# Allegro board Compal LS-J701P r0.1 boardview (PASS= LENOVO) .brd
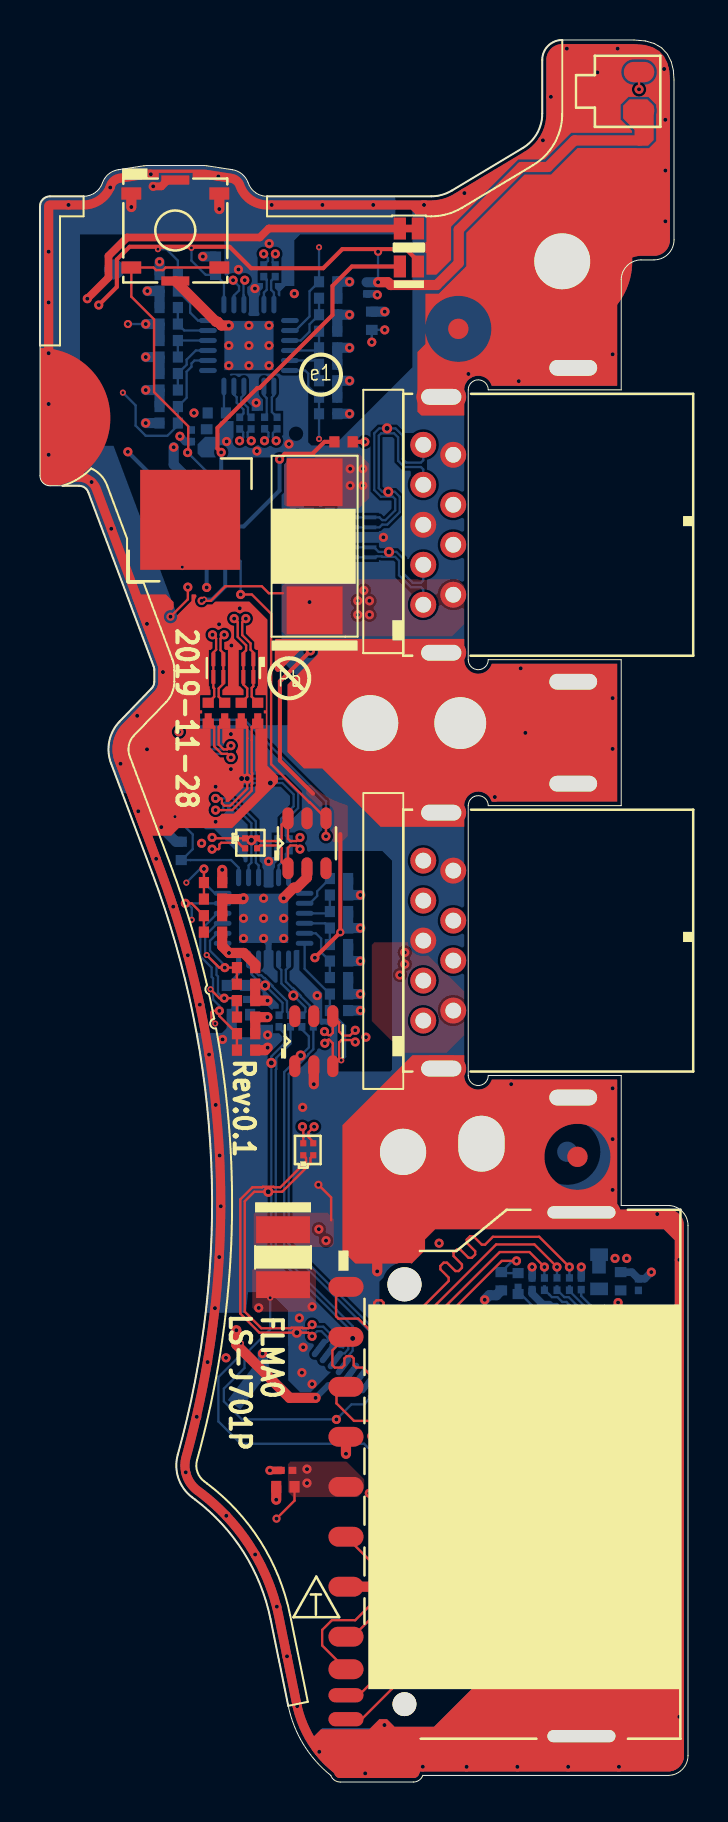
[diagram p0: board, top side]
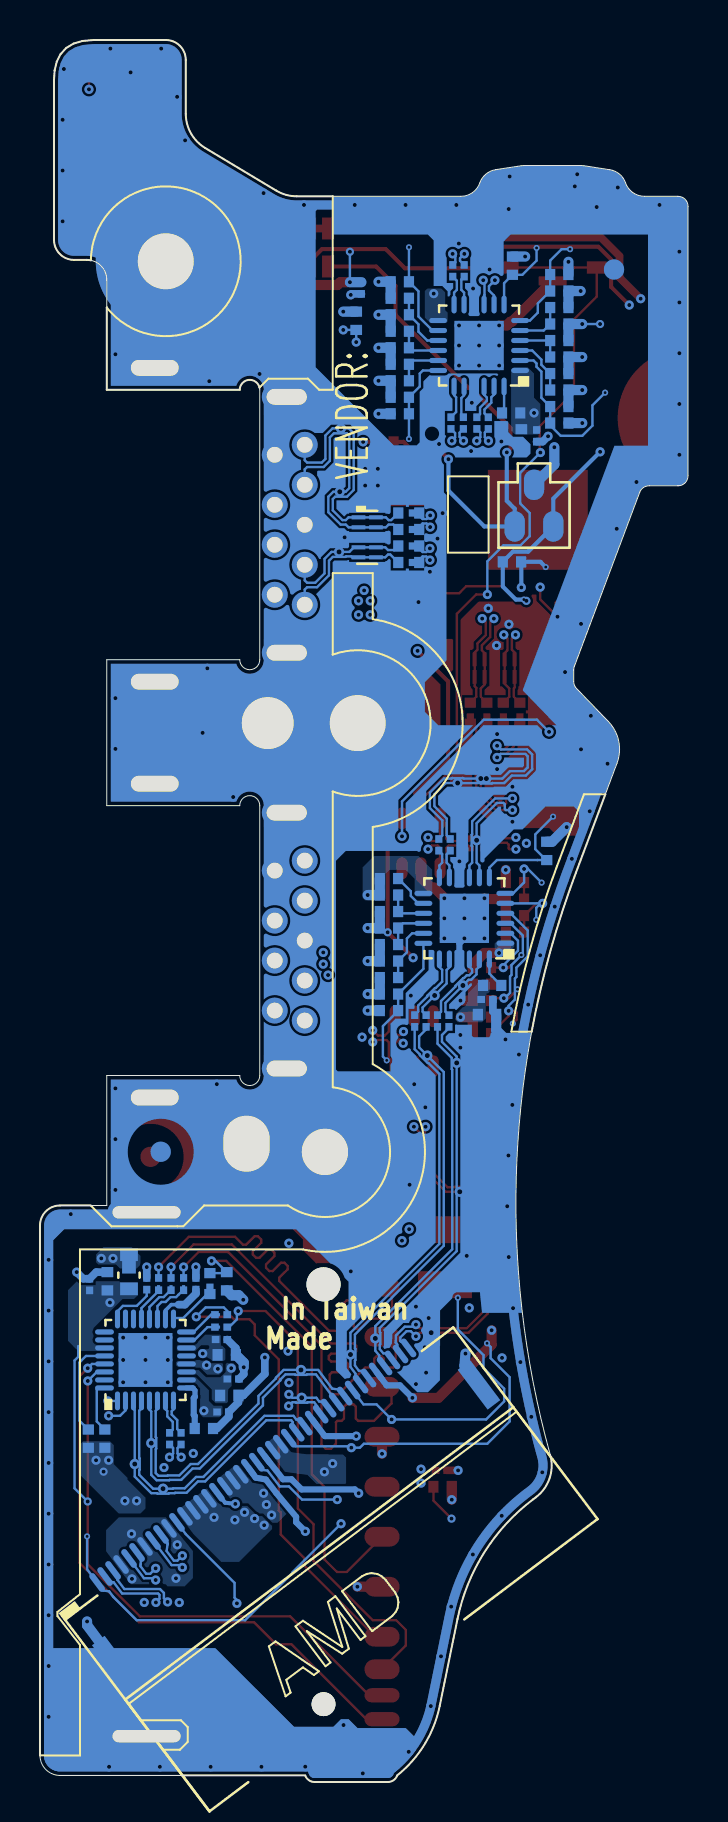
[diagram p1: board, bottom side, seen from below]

Outline 32.41 x 87.14 mm; copper layers: TOP, GND1, IN1, GND2, IN2, IN3, GND3, BOTTOM. Coordinates in mm from the lower left corner of the outline.
Outline path: 0,78.82 arc(0.15,79.17) 0.5,79.32 2.18,79.32 arc(2.76,79.5) 3.12,79.99 arc(3.43,80.43) 3.91,80.65 5.19,80.85 arc(5.27,80.86) 5.34,80.86 8.19,80.86 arc(8.27,80.86) 8.34,80.85 9.62,80.65 arc(10.11,80.43) 10.41,79.99 arc(10.78,79.5) 11.36,79.32 19.56,79.32 arc(20.1,79.39) 20.59,79.6 24.15,81.74 arc(24.86,82.47) 25.12,83.45 25.12,86.14 arc(25.41,86.85) 26.12,87.14 29.71,87.14 30.29,87.09 30.73,86.96 31.09,86.74 31.38,86.43 31.57,86.05 31.67,85.62 31.71,85.14 31.71,77.14 arc(31.41,76.43) 30.71,76.14 30.07,76.14 arc(29.36,75.85) 29.07,75.14 29.07,69.64 22.42,69.64 arc(21.92,70.14) 21.42,69.64 21.42,56.14 arc(21.92,55.64) 22.42,56.14 29.07,56.14 29.07,48.84 22.42,48.84 arc(21.92,49.34) 21.42,48.84 21.42,35.34 arc(21.92,34.84) 22.42,35.34 29.07,35.34 29.07,28.84 31.41,28.84 arc(32.11,28.55) 32.41,27.84 32.41,1.33 arc(32.11,0.62) 31.41,0.33 19.14,0.33 arc(18.96,0.09) 18.67,0 15.01,0 arc(14.73,0.09) 14.54,0.33 arc(13.17,1.88) 12.42,3.81 11.53,8.15 arc(10.19,11.49) 7.75,14.14 7.61,14.24 arc(6.92,15.19) 6.89,16.37 arc(8.56,31.02) 5.61,45.47 3.55,50.96 arc(3.47,52.07) 3.99,53.05 5.58,54.7 arc(5.68,54.86) 5.72,55.05 5.72,55.63 arc(5.71,55.72) 5.69,55.8 2.42,64.52 arc(2.23,64.75) 1.95,64.84 0.5,64.84 arc(0.15,64.99) 0,65.34 0,78.82

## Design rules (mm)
net group CLK: nets CLK_PCIE_N4 CLK_PCIE_P4
net group PCIE: nets PCIE_CRX_C_DTX_N9 PCIE_CRX_C_DTX_P9 PCIE_CRX_DTX_N9 PCIE_CRX_DTX_P9 PCIE_CTX_DRX_N9 PCIE_CTX_DRX_P9
net group USB3: nets USB3_CRX_C_RD_DTX_N1 USB3_CRX_C_RD_DTX_N2 USB3_CRX_C_RD_DTX_P1 USB3_CRX_C_RD_DTX_P2 USB3_CRX_DTX_N1 USB3_CRX_DTX_N2 USB3_CRX_DTX_P1 USB3_CRX_DTX_P2 USB3_CTX_C_RD_DRX_N1 USB3_CTX_C_RD_DRX_N2 USB3_CTX_C_RD_DRX_P1 USB3_CTX_C_RD_DRX_P2 USB3_CTX_DRX_N1 USB3_CTX_DRX_N2 USB3_CTX_DRX_P1 USB3_CTX_DRX_P2 USB3_RX3_CONN1_N1 USB3_RX3_CONN1_N1_R USB3_RX3_CONN1_P1 USB3_RX3_CONN1_P1_R USB3_RX3_CONN2_N2 USB3_RX3_CONN2_N2_R USB3_RX3_CONN2_P2 USB3_RX3_CONN2_P2_R USB3_TX3_CONN1_N1 USB3_TX3_CONN1_N1_R USB3_TX3_CONN1_P1 USB3_TX3_CONN1_P1_R USB3_TX3_CONN2_N2 USB3_TX3_CONN2_N2_R USB3_TX3_CONN2_P2 USB3_TX3_CONN2_P2_R USB3_TX3_MUX_N1_C USB3_TX3_MUX_N2_C USB3_TX3_MUX_P1_C USB3_TX3_MUX_P2_C
net group USB20: nets USB20_N1 USB20_N1_R USB20_N2 USB20_N2_R USB20_P1 USB20_P1_R USB20_P2 USB20_P2_R

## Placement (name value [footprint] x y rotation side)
CHS2  10P_0402_50V8J  [C_0402]  16.59 72.64 90 bottom
CHS3  0.1U_0201_10V6K  [C_0201]  16.33 74.44 90 bottom
CR1  0.1U_0201_10V K X5R  [C_0201]  25.93 16.88 90 bottom
CR2  0.1U_0201_10V K X5R  [C_0201]  25.35 16.88 90 bottom
CR3  0.1U_0201_10V6K  [C_0201]  23.04 20.16 180 bottom
CR4  4.7U_0402_6.3V6M  [C_0402]  29.04 24.59 90 bottom
CR5  10U_0402_6.3V6M  [C_0402]  23.4 19.33 180 bottom
CR6  0.1U_0201_10V6K  [C_0201]  23.55 18.51 180 bottom
CR7  4.7U_0402_6.3V6M  [C_0402]  23.53 21.37 180 bottom
CR8  0.1U_0201_10V6K  [C_0201]  23.63 22.13 180 bottom
CR9  1U_0201_6.3V6M  [C_0201]  24.61 24.63 90 bottom
CR12  5P_0402_50V8C  [C_0402]  23.07 25.51 270 bottom
CR13  0.1U_0201_10V6K  [C_0201]  29.93 24.59 90 bottom
CR14  1U_0201_6.3V6M  [C_0201]  27.07 24.63 90 bottom
CR15  4.7U_0402_6.3V6M  [C_0402]  12.73 14.77 180 top
CR16  0.1U_0201_10V K X5R  [C_0201]  12.63 15.59 180 top
CT11  0.01U_0402_16V7K  [C_0402]  8.34 67.67 270 bottom
CT12  0.1U_0201_10V K X5R  [C_0201]  11.86 68.27 270 bottom
CT13  0.1U_0201_10V K X5R  [C_0201]  11.23 68.27 270 bottom
CT14  0.1U_0201_10V K X5R  [C_0201]  7.57 67.63 270 bottom
CT15  0.1U_0201_10V K X5R  [C_0201]  10.56 67.68 90 bottom
CT16  0.1U_0201_10V K X5R  [C_0201]  9.99 67.68 90 bottom
CT17  0.1U_0201_10V K X5R  [C_0201]  11.77 75.3 90 bottom
CT18  0.1U_0201_10V K X5R  [C_0201]  11.19 75.3 90 bottom
CT23  0.01U_0402_16V7K  [C_0402]  10.51 38.38 180 bottom
CT24  0.1U_0201_10V K X5R  [C_0201]  12.46 46.59 90 bottom
CT25  0.1U_0201_10V K X5R  [C_0201]  11.89 46.59 90 bottom
CT26  0.1U_0201_10V K X5R  [C_0201]  10.34 39.15 180 bottom
CT27  0.1U_0201_10V K X5R  [C_0201]  12.53 37.77 90 bottom
CT28  0.1U_0201_10V K X5R  [C_0201]  11.96 37.77 90 bottom
CT29  0.1U_0201_10V K X5R  [C_0201]  13.1 38.36 270 bottom
CT30  0.1U_0201_10V K X5R  [C_0201]  13.67 38.36 270 bottom
CU31  150U_D2_6.3VM  [C_D2]  13.73 58.62 90 top
CU32  150U_B2_6.3VM_R35M  [C_B2]  12.16 27.63 90 top
D1  -  [L05ESDL5V0NA-4_SLP2510P8-10-9]  16.48 63.26 90 bottom
D2  AZC399-04S  [AZC099-04SPR7G_SOT23-6]  12.4 45.71 0 top
D3  -  [L05ESDL5V0NA-4_SLP2510P8-10-9]  10.67 56.16 0 top
D4  AZ5125-02S.R7G_SOT23-3  [AZ5125-02SPR7G_SOT23-3]  7.7 64.89 0 bottom
D5  AZC399-04S  [AZC099-04SPR7G_SOT23-6]  12.74 35.81 0 top
FD1  CF  [FIDUCIAL_C40M80]  20.92 72.69 0 top
FD2  CF  [FIDUCIAL_C40M80]  26.88 31.27 0 top
FD3  CF  [FIDUCIAL_C40M80]  3.7 75.66 180 bottom
FD4  CF  [FIDUCIAL_C40M80]  26.37 31.53 180 bottom
H1  HOLEA  [H_2P8]  26.12 76.07 0 top
H2  HOLEA  [H_2P8]  16.52 52.97 0 top
H3  HOLEA  [H_2P6]  21.02 52.97 0 top
H4  HOLEA  [H_2P3]  18.16 31.52 0 top
H5  HOLEA  [H_2P8X2P3]  22.08 31.93 90 top
JIO2  TWVM FPC0518-40RC-TAGHT 40P P.5  [HRS_TF31-40S-0P5SH-800_40P]  29.55 9.98 143 bottom
JSD1  T-SOL_156-1001902605~D  [T-SOL_156-1001902605_11P]  15.3 22.27 90 top
JUSB1  ACON_TAR2D-9U1397  [ACON_TAR2D-9U1397_9P]  20.67 59.39 90 top
JUSB2  ACON_TAR2D-9U1397  [ACON_TAR2D-9U1397_9P]  20.67 38.59 90 top
L1  DLM0NSN900HY2D_4P  [MURAT_DLM0NSN900HY2D_4P]  10.26 47.21 0 top
L2  DLM0NSN900HY2D_4P  [MURAT_DLM0NSN900HY2D_4P]  13.17 31.35 90 top
LED3  19-223-S2T1D-C30-2T_ORG-WHITE  [LED_19-223-S2T1D-C30-2T_4P]  18.9 75.81 90 top
NOREF  -  []  7.51 63.14 0 top
NOREF#2  -  []  -151.75 18.89 0 top
NOREF#3  -  []  -20.43 128.05 0 top
NOREF#4  -  []  3.76 -77.88 0 top
NOREF#5  -  []  26.12 76.07 0 top
NOREF#6  -  []  -161.91 14.7 0 top
NOREF#7  -  []  -139.94 19.02 0 top
NOREF#8  -  []  -9.51 85.12 0 top
RR1  6.2K_0402_1%  [R_0402]  24.67 17.68 180 bottom
RR2  10K_0402_5%  [R_0402]  29.99 17.63 270 bottom
RR3  0_0402_5%  [R0402_0OHM]  23.91 24.54 90 bottom
RR4  10K_0402_5%  [R_0402]  29.16 16.72 90 bottom
RR5  0_0603_5%  [R0603_0OHM]  27.96 26.07 270 bottom
RR6  0_0201_5%  [R0201_0OHM]  23.63 23.38 180 bottom
RR7  0_0201_5%  [R0201_0OHM]  23.63 22.75 180 bottom
RR8  0_0201_5%  [R0201_0OHM]  25.85 24.63 90 bottom
RR9  0_0201_5%  [R0201_0OHM]  26.48 24.63 90 bottom
RR10  0_0201_5%  [R0201_0OHM]  25.23 24.63 90 bottom
RS1  412_0402_1%  [R_0402]  8.35 61.04 0 bottom
RS2  412_0402_1%  [R_0402]  15.64 67.04 180 top
RT1  4.99K_0402_1%  [R_0402]  8.78 75.39 90 bottom
RT2  4.7K_0402_5%  [R_0402]  6.89 73.76 180 bottom
RT13  4.7K_0402_5%  [R_0402]  14.87 70.92 180 bottom
RT14  4.7K_0402_5%  [R_0402]  13.96 70.09 0 bottom
RT15  4.7K_0402_5%  [R_0402]  14.87 74.22 180 bottom
RT16  4.7K_0402_5%  [R_0402]  13.96 73.39 0 bottom
RT17  4.7K_0402_5%  [R_0402]  14.87 71.74 180 bottom
RT18  4.7K_0402_5%  [R_0402]  13.96 72.57 0 bottom
RT19  4.7K_0402_5%  [R_0402]  14.87 68.44 180 bottom
RT20  4.7K_0402_5%  [R_0402]  13.96 69.27 0 bottom
RT21  4.7K_0402_5%  [R_0402]  5.98 68.8 0 bottom
RT22  4.7K_0402_5%  [R_0402]  6.89 67.98 180 bottom
RT23  4.7K_0402_5%  [R_0402]  5.98 72.11 0 bottom
RT24  4.7K_0402_5%  [R_0402]  6.89 71.28 180 bottom
RT25  4.7K_0402_5%  [R_0402]  5.98 69.63 0 bottom
RT26  4.7K_0402_5%  [R_0402]  6.89 70.45 180 bottom
RT27  4.7K_0402_5%  [R_0402]  5.98 75.41 0 bottom
RT28  4.7K_0402_5%  [R_0402]  6.89 74.58 180 bottom
RT29  4.7K_0402_5%  [R_0402]  14.87 75.05 180 bottom
RT30  4.7K_0402_5%  [R_0402]  8.39 68.48 0 bottom
RT31  4.7K_0402_5%  [R_0402]  5.98 72.93 0 bottom
RT32  4.99K_0402_1%  [R_0402]  7.07 46.12 90 bottom
RT33  4.7K_0402_5%  [R_0402]  8.2 43.34 0 top
RT34  4.7K_0402_5%  [R_0402]  15.41 41.07 180 bottom
RT35  4.7K_0402_5%  [R_0402]  14.5 40.24 0 bottom
RT36  4.7K_0402_5%  [R_0402]  15.41 44.37 180 bottom
RT37  4.7K_0402_5%  [R_0402]  14.5 43.54 0 bottom
RT38  4.7K_0402_5%  [R_0402]  15.41 41.89 180 bottom
RT39  4.7K_0402_5%  [R_0402]  14.5 42.72 0 bottom
RT40  4.7K_0402_5%  [R_0402]  15.41 38.59 180 bottom
RT41  4.7K_0402_5%  [R_0402]  14.5 39.42 0 bottom
RT42  4.7K_0402_5%  [R_0402]  10.76 40.74 180 top
RT43  4.7K_0402_5%  [R_0402]  9.85 39.91 0 top
RT44  4.7K_0402_5%  [R_0402]  10.76 37.44 180 top
RT45  4.7K_0402_5%  [R_0402]  9.85 36.61 0 top
RT46  4.7K_0402_5%  [R_0402]  10.76 38.26 180 top
RT47  4.7K_0402_5%  [R_0402]  9.85 39.09 0 top
RT48  4.7K_0402_5%  [R_0402]  9.11 44.99 180 top
RT49  4.7K_0402_5%  [R_0402]  8.2 44.17 0 top
RT50  4.7K_0402_5%  [R_0402]  15.41 45.19 180 bottom
RT51  4.7K_0402_5%  [R_0402]  10.25 39.84 180 bottom
RT52  4.7K_0402_5%  [R_0402]  9.11 42.51 180 top
RT53  0_0402_5%  [R0402_0OHM]  13.58 62.65 0 bottom
RT54  0_0402_5%  [R0402_0OHM]  13.58 63.48 0 bottom
RT55  0_0402_5%  [R0402_0OHM]  10.06 53.07 90 top
RT56  0_0402_5%  [R0402_0OHM]  10.89 53.07 90 top
RT57  0_0402_5%  [R0402_0OHM]  13.58 61 0 bottom
RT58  0_0402_5%  [R0402_0OHM]  13.58 61.83 0 bottom
RT59  0_0402_5%  [R0402_0OHM]  9.24 53.07 90 top
RT60  0_0402_5%  [R0402_0OHM]  8.41 53.07 90 top
SW1  TJG-533-V-T/R_6P  [SW_TJG-533-V-T-R_6P]  4.57 79.46 90 top
UCR1  -  [RTS5232S-GR_QFN32_4X4]  28.53 19.06 90 bottom
UHS1  -  [APX8132AI-TRG_SOT23-3]  27.88 84.57 270 top
UT1  -  [PI3EQX7502AIZDEX_TQFN24_4X4]  8.4 70.61 90 bottom
UT2  -  [PI3EQX7502AIZDEX_TQFN24_4X4]  9.13 41.95 90 bottom

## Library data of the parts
CHS2 CR4 CR5 CR7 CR12 CR15 CT11 CT23 = C_0402
CHS3 CR1-CR3 CR6 CR8 CR9 CR13 CR14 CR16 CT12-CT18 CT24-CT30 = C_0201
CU31 = C_D2
CU32 = C_B2
D1 D3 = L05ESDL5V0NA-4_SLP2510P8-10-9
D2 D5 = AZC099-04SPR7G_SOT23-6
D4 = AZ5125-02SPR7G_SOT23-3
FD1-FD4 = FIDUCIAL_C40M80
H1 H2 = H_2P8
H3 = H_2P6
H4 = H_2P3
H5 = H_2P8X2P3
JIO2 = HRS_TF31-40S-0P5SH-800_40P
JSD1 = T-SOL_156-1001902605_11P
JUSB1 JUSB2 = ACON_TAR2D-9U1397_9P
L1 L2 = MURAT_DLM0NSN900HY2D_4P
LED3 = LED_19-223-S2T1D-C30-2T_4P
RR1 RR2 RR4 RS1 RS2 RT1 RT2 RT13-RT52 = R_0402
RR3 RT53-RT60 = R0402_0OHM
RR5 = R0603_0OHM
RR6-RR10 = R0201_0OHM
SW1 = SW_TJG-533-V-T-R_6P
UCR1 = RTS5232S-GR_QFN32_4X4
UHS1 = APX8132AI-TRG_SOT23-3
UT1 UT2 = PI3EQX7502AIZDEX_TQFN24_4X4

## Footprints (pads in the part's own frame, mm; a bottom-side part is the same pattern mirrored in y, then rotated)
ACON_TAR2D-9U1397_9P
  round 1.295 hole 0.787: 1(0,0) 2(2.5,0) 3(4.5,0) 4(7,0) 5(7.5,1.5) 6(5.5,1.5) 7(3.5,1.5) 8(1.5,1.5) 9(-0.5,1.5)
  oval 1.295x2.489 hole 0.787x2.007: 10(-2.9,0.6) 11(9.9,0.6)
  oval 1.295x2.896 hole 0.787x2.388: 12(-4.35,-6) 13(11.35,-6)
APX8132AI-TRG_SOT23-3
  oval 1.016x1.524 smd: 1(0,0) 2(0.965,2.083) 3(-0.965,2.083)
AZ5125-02SPR7G_SOT23-3
  oval 1.016x1.524 smd: 1(0,0) 2(0.965,2.083) 3(-0.965,2.083)
AZC099-04SPR7G_SOT23-6
  oval 0.559x1.092 smd: 1(0,0) 2(0.95,0) 3(1.9,0) 4(1.9,2.5) 5(0.95,2.5) 6(0,2.5)
C_0201
  rect 0.381x0.356 smd: 1(0,0) 2(0.584,0)
C_0402
  rect 0.508x0.584 smd: 1(0,0) 2(0.914,0)
C_B2
  rect 1.346x2.692 smd: 1(0,0) 2(-2.75,0)
C_D2
  rect 2.388x2.794 smd: 1(0,0) 2(6.4,0)
FIDUCIAL_C40M80
  round 1.016 smd: 1(0,0)
H_2P3
  round 2.819 hole 2.311: 1(0,0)
H_2P6
  round 3.099 hole 2.591: 1(0,0)
H_2P8
  round 3.302 hole 2.794: 1(0,0)
H_2P8X2P3
  oval 3.302x2.819 hole 2.794x2.311: 1(0,0)
HRS_TF31-40S-0P5SH-800_40P
  oval 0.305x1.092 smd: 1(0,0) 2(0.5,0) 3(1,0) 4(1.5,0) 5(2,0) 6(2.5,0) 7(3,0) 8(3.5,0) 9(4,0) 10(4.5,0) 11(5,0) 12(5.5,0) 13(6,0) 14(6.5,0) 15(7,0) 16(7.5,0) 17(8,0) 18(8.5,0) 19(9,0) 20(9.5,0) 21(10,0) 22(10.5,0) 23(11,0) 24(11.5,0) 25(12,0) 26(12.5,0) 27(13,0) 28(13.5,0) 29(14,0) 30(14.5,0) 31(15,0) 32(15.5,0) 33(16,0) 34(16.5,0) 35(17,0) 36(17.5,0) 37(18,0) 38(18.5,0) 39(19,0) 40(19.5,0)
  rect 0.787x2.489 smd: 41(-1.7,-3.6) 42(21.2,-3.6)
L05ESDL5V0NA-4_SLP2510P8-10-9
  rect 0.203x0.686 smd: 1(0,0) 2(-0.5,0) 4(-1.5,0) 5(-2,0) 6(-2,-0.875) 7(-1.5,-0.875) 8(-0.5,-0.875) 9(0,-0.875)
  rect 0.406x1.549 smd: 3(-1,-0.437)
LED_19-223-S2T1D-C30-2T_4P
  rect 1.092x0.61 smd: 1(0,0) 2(1.9,0) 3(0,0.9) 4(1.9,0.9)
MURAT_DLM0NSN900HY2D_4P
  rect 0.305x0.305 smd: 1(0,0) 2(0.6,0) 3(0.6,-0.5) 4(0,-0.5)
PI3EQX7502AIZDEX_TQFN24_4X4
  oval 0.254x0.889 smd: 1(0,0) 2(0.5,0) 3(1,0) 4(1.5,0) 5(2,0) 6(2.5,0) 13(2.5,4.1) 14(2,4.1) 15(1.5,4.1) 16(1,4.1) 17(0.5,4.1) 18(0,4.1)
  oval 0.889x0.254 smd: 7(3.3,0.8) 8(3.3,1.3) 9(3.3,1.8) 10(3.3,2.3) 11(3.3,2.8) 12(3.3,3.3) 19(-0.8,3.3) 20(-0.8,2.8) 21(-0.8,2.3) 22(-0.8,1.8) 23(-0.8,1.3) 24(-0.8,0.8)
  rect 2.464x2.464 smd: 25(1.25,2.05)
R0201_0OHM
  custom 0.089x0.089 smd: 1(0,0)
  rect 0.381x0.356 smd: 2(0.584,0)
R0402_0OHM
  custom 0.14x0.14 smd: 1(0,0)
  rect 0.508x0.559 smd: 2(0.914,0)
R0603_0OHM
  custom 0.222x0.222 smd: 1(0,0)
  rect 0.635x0.889 smd: 2(1.397,0)
R_0402
  rect 0.508x0.559 smd: 1(0,0) 2(0.914,0)
RTS5232S-GR_QFN32_4X4
  oval 0.94x0.254 smd: 1(0,0) 2(0,-0.4) 3(0,-0.8) 4(0,-1.2) 5(0,-1.6) 6(0,-2) 7(0,-2.4) 8(0,-2.8) 17(4.1,-2.8) 18(4.1,-2.4) 19(4.1,-2) 20(4.1,-1.6) 21(4.1,-1.2) 22(4.1,-0.8) 23(4.1,-0.4) 24(4.1,0)
  oval 0.254x0.94 smd: 9(0.65,-3.45) 10(1.05,-3.45) 11(1.45,-3.45) 12(1.85,-3.45) 13(2.25,-3.45) 14(2.65,-3.45) 15(3.05,-3.45) 16(3.45,-3.45) 25(3.45,0.65) 26(3.05,0.65) 27(2.65,0.65) 28(2.25,0.65) 29(1.85,0.65) 30(1.45,0.65) 31(1.05,0.65) 32(0.65,0.65)
  rect 2.692x2.692 smd: 33(2.05,-1.4)
SW_TJG-533-V-T-R_6P
  rect 0.61x0.991 smd: 1(0,0) 2(0,-4.4) 3(-3.7,0) 4(-3.7,-4.4)
  rect 0.457x1.397 smd: 5(0.675,-2.2) 6(-4.375,-2.2)
T-SOL_156-1001902605_11P
  round 1.194 hole 1.194 unplated: (-18.375,-2.925)
  round 1.702 hole 1.702 unplated: (2.625,-2.925)
  oval 0.991x1.753 smd: 1(0,0) 2(-2.5,0) 3(-5,0) 4(-7.5,0) 5(-10,0) 6(-12.5,0) 7(-15,0) 8(-16.63,0) 9(2.5,0)
  oval 0.711x1.753 smd: 10(-17.93,0) 11(-19.13,0)
  rect 1.499x2.794 smd: 12(-20.525,-1.925)
  oval 1.194x3.912 hole 0.61x3.404: 13(-19.975,-11.775) 14(6.225,-11.775)
  rect 1.473x2.794 smd: 15(4.425,-1.925)

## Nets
+3VALW: CT11.1 CT14.1 CT23.1 CT26.1 JIO2.22 RT13.1 RT15.1 RT17.1 RT19.1 RT21.1 RT23.1 RT25.1 RT27.1 RT29.1 RT30.1 RT31.1 RT34.1 RT36.1 RT38.1 RT40.1 RT42.1 RT44.1 RT46.1 RT48.1 RT50.1 RT51.1 RT52.1 UT1.1 UT1.13 UT2.1 UT2.13
+3VL: CHS3.2 JIO2.36 UHS1.2
+3VS: JIO2.23 JIO2.24 RR2.2 RR4.1 RR5.1
+3VS_SD: CR3.1 CR4.1 CR5.1 CR13.1 RR5.2 UCR1.11 UCR1.27
+5VALW_USB1: CU31.1 JIO2.12 JIO2.13 JIO2.14 JIO2.15 JUSB1.1
+5VALW_USB2: CU32.1 JIO2.17 JIO2.18 JIO2.19 JUSB2.1
+5VL: JIO2.20 LED3.2 LED3.4
+DV33_18: CR9.1 UCR1.18
GND: CHS2.2 CHS3.1 CR3.2 CR4.2 CR5.2 CR6.2 CR7.2 CR8.2 CR9.2 CR12.2 CR13.2 CR14.2 CR15.2 CR16.2 CT11.2 CT14.2 CT23.2 CT26.2 CU31.2 CU32.2 D1.3 D2.2 D3.3 D4.1 D5.2 H1.1(TP-1) H2.1(TP-1) H3.1(TP-1) H4.1(TP-1) H5.1(TP-1) JIO2.4 JIO2.7 JIO2.10 JIO2.28 JIO2.41 JIO2.42 JSD1.3 JSD1.6 JSD1.12 JSD1.13 JSD1.14 JSD1.15 JUSB1.4 JUSB1.7 JUSB1.10 JUSB1.11 JUSB1.12 JUSB1.13 JUSB2.4 JUSB2.7 JUSB2.10 JUSB2.11 JUSB2.12 JUSB2.13 RR1.2 RT1.2 RT2.2 RT14.2 RT16.2 RT18.2 RT20.2 RT22.2 RT24.2 RT26.2 RT28.2 RT32.2 RT33.2 RT35.2 RT37.2 RT39.2 RT41.2 RT43.2 RT45.2 RT47.2 RT49.2 SW1.1 SW1.2 SW1.5 SW1.6 UCR1.33 UHS1.1 UT1.10 UT1.21 UT1.25 UT2.10 UT2.21 UT2.25
+CARD_3V3: CR15.1 CR16.1 JSD1.4 UCR1.12
CLK_PCIE_N4: JIO2.32 UCR1.6
CLK_PCIE_P4: JIO2.31 UCR1.5
CLKREQ_PCIE#4: JIO2.33 UCR1.2
I2C_EN1_U1: RT30.2 UT1.24
I2C_EN1_U2: RT51.2 UT2.24
LID_SW#: CHS2.1 JIO2.1 UHS1.3
ON/OFF#: D2.4 JIO2.11 SW1.3 SW1.4
P3_U1_A_DE0: RT25.2 RT26.1 UT1.3
P3_U1_A_DE1: RT27.2 RT28.1 UT1.6
P3_U1_A_EQ0: RT21.2 RT22.1 UT1.2
P3_U1_A_EQ1: RT23.2 RT24.1 UT1.4
P3_U1_B_DE0: RT17.2 RT18.1 UT1.16
P3_U1_B_DE1: RT19.2 RT20.1 UT1.18
P3_U1_B_EQ0: RT13.2 RT14.1 UT1.17
P3_U1_B_EQ1: RT15.2 RT16.1 UT1.15
P3_U2_A_DE0: RT46.2 RT47.1 UT2.3
P3_U2_A_DE1: RT48.2 RT49.1 UT2.6
P3_U2_A_EQ0: RT42.2 RT43.1 UT2.2
P3_U2_A_EQ1: RT44.2 RT45.1 UT2.4
P3_U2_B_DE0: RT38.2 RT39.1 UT2.16
P3_U2_B_DE1: RT40.2 RT41.1 UT2.18
P3_U2_B_EQ0: RT34.2 RT35.1 UT2.17
P3_U2_B_EQ1: RT36.2 RT37.1 UT2.15
PCI_RST#: JIO2.25 UCR1.1
PCIE_CRX_C_DTX_N9: CR2.2 UCR1.8
PCIE_CRX_C_DTX_P9: CR1.2 UCR1.7
PCIE_CRX_DTX_N9: CR2.1 JIO2.30
PCIE_CRX_DTX_P9: CR1.1 JIO2.29
PCIE_CTX_DRX_N9: JIO2.27 UCR1.4
PCIE_CTX_DRX_P9: JIO2.26 UCR1.3
PCIE_WAKE#: RR4.2 UCR1.32
PD#_1_U1: RT2.1 RT31.2 UT1.5
PD#_1_U2: RT33.1 RT52.2 UT2.5
PWR_LED#: JIO2.21 RS1.1
PWR_LED#_R: D4.3 LED3.1 RS1.2
PWR_LED_AMBER#: JIO2.16 RS2.1
PWR_LED_AMBER#_R: D4.2 LED3.3 RS2.2
SD_CD#: JSD1.10 UCR1.30
SD_CLK: RR3.1 UCR1.17
SD_CLK_R: CR12.1 JSD1.5 RR3.2
SD_CMD: RR10.1 UCR1.19
SD_CMD_R: JSD1.2 RR10.2
SD_D0: RR6.1 UCR1.16
SD_D0_R: JSD1.7 RR6.2
SD_D1: RR7.1 UCR1.15
SD_D1_R: JSD1.8 RR7.2
SD_D2: RR9.1 UCR1.21
SD_D2_R: JSD1.9 RR9.2
SD_D3: RR8.1 UCR1.20
SD_D3_R: JSD1.1 RR8.2
SD_WP: JSD1.11 UCR1.29
TEST3_U1: RT29.2 UT1.14
TEST3_U2: RT50.2 UT2.14
USB3_CRX_C_RD_DTX_N1: CT16.2 UT1.23
USB3_CRX_C_RD_DTX_N2: CT28.2 UT2.23
USB3_CRX_C_RD_DTX_P1: CT15.2 UT1.22
USB3_CRX_C_RD_DTX_P2: CT27.2 UT2.22
USB3_CRX_DTX_N1: CT16.1 JIO2.8
USB3_CRX_DTX_N2: CT28.1 JIO2.38
USB3_CRX_DTX_P1: CT15.1 JIO2.9
USB3_CRX_DTX_P2: CT27.1 JIO2.37
USB3_CTX_C_RD_DRX_N1: CT13.1 UT1.20
USB3_CTX_C_RD_DRX_N2: CT29.1 UT2.20
USB3_CTX_C_RD_DRX_P1: CT12.1 UT1.19
USB3_CTX_C_RD_DRX_P2: CT30.1 UT2.19
USB3_CTX_DRX_N1: CT13.2 JIO2.5
USB3_CTX_DRX_N2: CT29.2 JIO2.35
USB3_CTX_DRX_P1: CT12.2 JIO2.6
USB3_CTX_DRX_P2: CT30.2 JIO2.34
USB3_RX3_CONN1_N1: RT54.1 UT1.8
USB3_RX3_CONN1_N1_R: D1.1 D1.9 JUSB1.5 RT54.2
USB3_RX3_CONN1_P1: RT53.1 UT1.9
USB3_RX3_CONN1_P1_R: D1.2 D1.8 JUSB1.6 RT53.2
USB3_RX3_CONN2_N2: RT56.1 UT2.8
USB3_RX3_CONN2_N2_R: D3.1 D3.9 JUSB2.5 RT56.2
USB3_RX3_CONN2_P2: RT55.1 UT2.9
USB3_RX3_CONN2_P2_R: D3.2 D3.8 JUSB2.6 RT55.2
USB3_TX3_CONN1_N1: CT18.2 RT58.1
USB3_TX3_CONN1_N1_R: D1.4 D1.7 JUSB1.8 RT58.2
USB3_TX3_CONN1_P1: CT17.2 RT57.1
USB3_TX3_CONN1_P1_R: D1.5 D1.6 JUSB1.9 RT57.2
USB3_TX3_CONN2_N2: CT25.2 RT59.1
USB3_TX3_CONN2_N2_R: D3.4 D3.7 JUSB2.8 RT59.2
USB3_TX3_CONN2_P2: CT24.2 RT60.1
USB3_TX3_CONN2_P2_R: D3.5 D3.6 JUSB2.9 RT60.2
USB3_TX3_MUX_N1_C: CT18.1 UT1.11
USB3_TX3_MUX_N2_C: CT25.1 UT2.11
USB3_TX3_MUX_P1_C: CT17.1 UT1.12
USB3_TX3_MUX_P2_C: CT24.1 UT2.12
USB20_N1: JIO2.2 L1.1
USB20_N1_R: D2.6 JUSB1.2 L1.2
USB20_N2: JIO2.39 L2.4
USB20_N2_R: D5.4 JUSB2.2 L2.3
USB20_P1: JIO2.3 L1.4
USB20_P1_R: D2.1 JUSB1.3 L1.3
USB20_P2: JIO2.40 L2.1
USB20_P2_R: D5.3 JUSB2.3 L2.2
N111995914: RT1.1 UT1.7
N112008691: RR1.1 UCR1.9
N112008714: RR2.1 UCR1.28
N112008722: CR6.1 CR7.1 CR8.1 UCR1.10 UCR1.14
N112008758: CR14.1 UCR1.24
N112013174: RT32.1 UT2.7

Pads without a net: D2 3 5; D5 1 5 6; FD1 1; FD2 1; FD3 1; FD4 1; UCR1 13 22 23 25 26 31

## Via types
v1: diameter 0.457, hole 0.203, TOP to BOTTOM, 319 vias
v2: diameter 0.406, hole 0.203, TOP to BOTTOM, 12 vias
v3: diameter 0.305, hole 0.152, TOP to BOTTOM, 17 vias
v4: diameter 0.508, hole 0.254, TOP to BOTTOM, 20 vias

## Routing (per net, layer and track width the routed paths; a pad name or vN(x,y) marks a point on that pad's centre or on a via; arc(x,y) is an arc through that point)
+3VALW: length 74.5
  TOP w0.508: RT52.1 9.11,41.81 v1(9.45,41.47) 10.19,41.47 10.76,40.9 RT42.1 ; v1(11.37,38.26) RT46.1 RT44.1 ; RT48.1 v1(9.11,45.63)
  IN2 w0.508: 12.53,38.57 12.34,38.38 12.34,18.13 15.45,15.02 15.9,15.02 v1(16.47,14.44)
  IN3 w0.508: v1(9.11,45.63) 8.55,45.06 7.95,45.06 7.38,45.63 7.38,49.31 8.02,49.94 8.02,58.26 9.1,59.34 9.1,65.61 8.45,66.26 8.45,66.3 7.7,67.05 v1(7.7,68.48)
  BOTTOM w0.117: v1(5.29,72.93) v2(4.4,72.93)
  BOTTOM w0.305: v1(16.47,14.44) 16.66,14.64 19.32,14.64 19.83,15.14 20.25,15.14 JIO2.22
  BOTTOM w0.508: RT38.1 RT34.1 v1(16.02,41.07) ; v1(5.29,72.93) RT31.1 RT23.1 ; v1(15.48,71.74) RT17.1 RT13.1 ; v1(16.02,44.37) RT36.1 RT50.1 ; RT40.1 v1(16.02,38.59) ; v1(5.29,69.63) RT25.1 RT21.1 ; v1(15.48,75.05) RT29.1 RT15.1 ; RT27.1 v1(5.98,76.04) ; RT19.1 v1(15.48,68.44)
  vias: v1(12.72,74.45)
+3VL: length 89.5
  TOP w0.508: 30,82.12 26.73,82.12 25.4,80.79 24.08,80.79 20.94,77.65 20.94,75.98 19.84,74.88 17.53,74.88 17.39,75.02 v1(16.91,75.02) ; v1(13.78,19.22) 12.48,19.22 9.82,21.88 v1(9.82,22.6)
  IN3 w0.508: v1(9.82,22.6) 9.82,39.47 9.31,39.98 9.14,39.98 8.63,40.49 8.63,43.48 6.78,45.33 6.75,45.41 6.75,51.66 6.34,52.06 6.34,52.78 7.05,53.49 7.05,57.61 6.03,58.62 6.03,68.87 7.38,70.23 11.69,70.23 12.2,70.74 12.2,70.98 15.23,74 15.3,74 16.32,75.02 v1(16.91,75.02)
  BOTTOM w0.117: v1(16.91,75.02) v2(16.91,76.55)
  BOTTOM w0.305: v1(13.78,19.22) 14.41,19.84 15.07,19.84 JIO2.36
  BOTTOM w0.508: CHS3.2 v1(16.91,75.02)
+3VS: length 19.2
  IN2 w1.016: 18.81,14.51 18.81,14.25 18.83,14.25 20,13.08 20,12.28 21.72,10.57 22.5,10.57 25.29,7.78 28.15,7.78 29.61,9.24 29.61,11.9 28.4,13.11
  vias: v1(17.77,15.93) v1(18.18,15.52) v1(27.58,14.06) v1(28.16,14.06) v1(28.76,26.19) v1(28.97,16.1) v1(29.34,26.19) v1(29.6,16.1) v2(29.23,15.52)
+3VS_SD: length 16.7
  IN1 w0.508: v1(28.91,23.98) 24.16,23.98 23.42,23.25 23.42,21.5 22.9,20.98 22.9,20.76 v1(22.85,20.7)
  BOTTOM w0.117: v2(30.02,14.03) 30.68,14.69 30.68,21.09 30.5,21.27 30.5,21.81
+5VALW_USB1: length 4.5
  TOP w0.117: 12.15,59.47 11.44,59.47 11.09,59.81 9.27,59.81 8.54,59.09 v2(8.08,59.09)
  vias: v1(15.89,59.09) v1(15.89,58.39) v1(16.2,59.6) v1(16.48,59.09) v1(16.48,58.39) v1(21.2,12.85) v1(21.68,13.18) v1(22.18,13.49) v1(22.66,13.11) v1(23.7,13.24)
+5VALW_USB2: length 2
  TOP w0.117: 14.56,28.1 14.56,29.24 v2(13.92,29.88)
  vias: v1(13.95,27.65) v1(14.31,27.08) v1(18,40.37) v1(18.24,41.5) v1(18.24,40.91) v1(20.83,13.35) v1(21.08,13.88) v1(21.23,14.44)
+5VL: length 96.5
  TOP w0.117: v2(6.53,58.29) 7.39,59.16 v1(7.39,59.77)
  TOP w0.381: v1(2.37,74.2) 3.42,75.26 3.42,76.33 4.35,77.26 10.99,77.26 11.44,77.71 LED3.4 LED3.2
  IN1 w0.381: v1(7.39,59.77) 7.39,62.77 2.37,67.79 v1(2.37,74.2)
  IN2 w0.381: v1(19.14,12.54) 18.82,12.22 15.13,12.22 12.59,14.76 12.59,16.19 11.7,17.08 11.7,33.91 10.01,35.6 10.01,39.54 9.54,40.01 9.11,40.01 8.53,40.59 8.53,44.42 7.51,45.43 7.51,59.65 v1(7.39,59.77)
  BOTTOM w0.305: JIO2.20 21.62,15.23 21.11,15.13 20.58,14.45 19.6,13.26 19.6,13 v1(19.14,12.54)
+DV33_18: length 2.5
  BOTTOM w0.178: UCR1.18 26.13,23.59 25.84,23.88 25.48,23.88
  BOTTOM w0.381: 25.48,23.88 25.16,23.88 24.61,24.43 CR9.1
GND: length 587.7
  TOP w0.381: SW1.5 6.39,80.13 6.07,79.82 v1(5.66,79.82) ; CR16.2 v1(11.5,15.59)
  TOP w0.406: D3.3 9.67,56.75 v1(9.57,56.85)
  TOP w0.508: SW1.2 v1(8.97,78.68) ; RT43.2 10.76,39.09 RT47.2 v1(11.38,39.09) ; v1(12.19,44.21) 12.19,44.23 12.69,44.74 12.84,44.74 13.35,45.24 D2.2 ; 17.23,1.74 v1(17.23,2.85) ; v1(16.86,25.54) 16.86,26.09 17.23,26.45 JSD1.15 ; RT33.2 9.11,43.34 RT49.2 10.14,44.17 v1(10.18,44.21) ; CR15.2 v1(11.81,14.12) ; SW1.6 8.81,73.05 8.88,73.05 9.07,72.86 v1(9.45,72.86) ; RT45.2 11.26,36.61 v1(11.38,36.73) ; D5.2 v1(13.69,34.9) ; JSD1.3 v1(15.3,16.42) ; UHS1.1 v1(27.88,85.52) ; JSD1.6 v1(16.53,9.77) ; SW1.1 v1(4.57,78.78)
  GND1 w0.254: JSD1.13 29.21,3.07 ; JSD1.13 29.21,2.29 ; JSD1.13 29.21,1.52 ; JSD1.13 24.94,3.07 ; JSD1.13 24.94,2.29 ; JSD1.13 27.08,1.52 ; JSD1.13 24.94,1.52 ; JSD1.13 27.08,3.07 ; 20.67,44.76 JUSB2.4 ; JUSB2.4 20.67,46.42 ; JUSB2.4 20.03,44.95 ; H2.1 17.86,54.31 ; H2.1 17.86,51.63 ; H2.1 18.35,52.97 ; H2.1 14.69,52.97 ; H2.1 15.17,54.31 ; H2.1 15.17,51.63 ; H2.1 16.52,54.8 ; H2.1 16.52,51.14 ; 18.16,29.93 H4.1 ; H4.1 19.75,31.52 ; H4.1 19.33,30.35 ; H4.1 16.98,30.35 ; H4.1 16.98,32.69 ; H4.1 18.16,33.11 ; H4.1 16.57,31.52 ; H4.1 19.33,32.69 ; 26.67,33.41 JUSB2.12 ; JUSB2.12 25.04,34.24 ; JUSB2.12 25.04,33.41 ; JUSB2.12 28.29,34.24 ; JUSB2.12 28.29,33.41 ; 21.02,51.24 H3.1 ; H3.1 19.74,54.24 ; H3.1 19.29,52.97 ; H3.1 22.29,51.7 ; H3.1 22.75,52.97 ; H3.1 21.02,54.7 ; H3.1 19.74,51.7 ; H3.1 22.29,54.24 ; JUSB1.4 20.67,67.22 ; JUSB1.4 20.03,65.75 ; JUSB1.4 20.67,65.56 ; 25.04,55.04 JUSB1.12 ; JUSB1.12 28.29,55.04 ; JUSB1.12 25.04,54.21 ; JUSB1.12 26.67,54.21 ; JUSB1.12 28.29,54.21 ; 18.64,55.66 JUSB1.10 ; JUSB1.10 18.64,57.32 ; JUSB1.10 18.64,56.49 ; JUSB1.10 20.07,55.66 ; JUSB1.10 20.07,57.32 ; 24.77,77.41 H1.1 ; H1.1 24.77,74.73 ; H1.1 26.12,77.9 ; H1.1 24.29,76.07 ; H1.1 27.46,74.73 ; H1.1 27.95,76.07 ; H1.1 26.12,74.24 ; H1.1 27.46,77.41 ; 25.04,70.74 JUSB1.13 ; JUSB1.13 26.67,71.57 ; JUSB1.13 25.04,71.57 ; JUSB1.13 28.29,70.74 ; JUSB1.13 28.29,71.57 ; H5.1 22.08,33.76 ; H5.1 20.49,30.1 ; H5.1 20.49,31.93 ; H5.1 23.67,30.1 ; H5.1 20.49,33.76 ; H5.1 23.67,33.76 ; H5.1 22.08,30.1 ; H5.1 23.67,31.93 ; 25.04,50.77 JUSB2.13 ; JUSB2.13 28.29,50.77 ; JUSB2.13 25.04,49.94 ; JUSB2.13 28.29,49.94 ; JUSB2.13 26.67,50.77 ; 18.64,70.12 JUSB1.11 ; JUSB1.11 20.07,70.12 ; JUSB1.11 18.64,69.29 ; JUSB1.11 18.64,68.46 ; JUSB1.11 20.07,68.46 ; JUSB2.10 20.07,36.52 ; JUSB2.10 18.64,35.69 ; JUSB2.10 18.64,34.86 ; JUSB2.10 18.64,36.52 ; JUSB2.10 20.07,34.86 ; 19.17,62.06 JUSB1.7 ; JUSB1.7 19.8,63.52 ; JUSB1.7 19.99,62.89 ; JUSB1.7 19.17,63.72 ; JUSB1.7 19.8,62.25 ; JUSB1.7 18.34,62.89 ; JUSB1.7 18.53,63.52 ; JUSB1.7 18.53,62.25 ; JUSB2.7 19.17,42.92 ; JUSB2.7 18.34,42.09 ; JUSB2.7 19.17,41.26 ; JUSB2.7 19.99,42.09 ; JUSB2.7 18.53,42.72 ; JUSB2.7 19.8,42.72 ; JUSB2.7 19.8,41.45 ; 18.64,48.49 JUSB2.11 ; JUSB2.11 18.64,47.66 ; JUSB2.11 20.07,49.32 ; JUSB2.11 18.64,49.32 ; JUSB2.11 20.07,47.66 ; JSD1.14 29.21,27.72 ; JSD1.14 24.94,29.27 ; JSD1.14 24.94,28.49 ; JSD1.14 24.94,27.72 ; JSD1.14 27.08,27.72 ; JSD1.14 29.21,28.49 ; JSD1.14 27.08,29.27
  GND2 w0.254: 25.04,33.41 JUSB2.12 ; JUSB2.12 25.04,34.24 ; JUSB2.12 26.67,33.41 ; JUSB2.12 28.29,34.24 ; JUSB2.12 28.29,33.41 ; 20.07,55.66 JUSB1.10 ; JUSB1.10 20.07,57.32 ; JUSB1.10 18.64,55.66 ; JUSB1.10 18.64,56.49 ; JUSB1.10 18.64,57.32 ; 16.98,32.69 H4.1 ; H4.1 19.75,31.52 ; H4.1 18.16,29.93 ; H4.1 19.33,32.69 ; H4.1 18.16,33.11 ; H4.1 16.57,31.52 ; H4.1 19.33,30.35 ; H4.1 16.98,30.35 ; 24.94,1.52 JSD1.13 ; JSD1.13 24.94,3.07 ; JSD1.13 29.21,1.52 ; JSD1.13 29.21,2.29 ; JSD1.13 24.94,2.29 ; JSD1.13 27.08,1.52 ; JSD1.13 27.08,3.07 ; JSD1.13 29.21,3.07 ; 19.74,54.24 H3.1 ; H3.1 22.29,51.7 ; H3.1 22.75,52.97 ; H3.1 21.02,54.7 ; H3.1 19.74,51.7 ; H3.1 21.02,51.24 ; H3.1 22.29,54.24 ; H3.1 19.29,52.97 ; 16.52,51.14 H2.1 ; H2.1 17.86,51.63 ; H2.1 14.69,52.97 ; H2.1 18.35,52.97 ; H2.1 15.17,51.63 ; H2.1 15.17,54.31 ; H2.1 17.86,54.31 ; H2.1 16.52,54.8 ; 20.07,68.46 JUSB1.11 ; JUSB1.11 18.64,69.29 ; JUSB1.11 18.64,70.12 ; JUSB1.11 20.07,70.12 ; JUSB1.11 18.64,68.46 ; JSD1.14 29.21,28.49 ; JSD1.14 24.94,28.49 ; JSD1.14 27.08,29.27 ; JSD1.14 24.94,27.72 ; JSD1.14 29.21,27.72 ; JSD1.14 24.94,29.27 ; JSD1.14 27.08,27.72 ; 20.49,31.93 H5.1 ; H5.1 20.49,33.76 ; H5.1 23.67,33.76 ; H5.1 22.08,33.76 ; H5.1 20.49,30.1 ; H5.1 23.67,31.93 ; H5.1 22.08,30.1 ; H5.1 23.67,30.1 ; 20.03,65.75 JUSB1.4 ; JUSB1.4 20.67,65.56 ; JUSB1.4 20.67,67.22 ; JUSB2.4 20.67,46.42 ; JUSB2.4 20.03,44.95 ; JUSB2.4 20.67,44.76 ; 20.07,47.66 JUSB2.11 ; JUSB2.11 18.64,48.49 ; JUSB2.11 18.64,49.32 ; JUSB2.11 18.64,47.66 ; JUSB2.11 20.07,49.32 ; 24.77,74.73 H1.1 ; H1.1 26.12,77.9 ; H1.1 24.77,77.41 ; H1.1 27.95,76.07 ; H1.1 24.29,76.07 ; H1.1 26.12,74.24 ; H1.1 27.46,77.41 ; H1.1 27.46,74.73 ; 18.64,36.52 JUSB2.10 ; JUSB2.10 18.64,35.69 ; JUSB2.10 20.07,34.86 ; JUSB2.10 20.07,36.52 ; JUSB2.10 18.64,34.86 ; 18.53,63.52 JUSB1.7 ; JUSB1.7 19.99,62.89 ; JUSB1.7 19.17,63.72 ; JUSB1.7 18.53,62.25 ; JUSB1.7 19.8,63.52 ; JUSB1.7 19.8,62.25 ; JUSB1.7 18.34,62.89 ; JUSB1.7 19.17,62.06 ; JUSB1.13 26.67,71.57 ; JUSB1.13 28.29,70.74 ; JUSB1.13 28.29,71.57 ; JUSB1.13 25.04,70.74 ; JUSB1.13 25.04,71.57 ; JUSB1.12 28.29,54.21 ; JUSB1.12 28.29,55.04 ; JUSB1.12 25.04,54.21 ; JUSB1.12 25.04,55.04 ; JUSB1.12 26.67,54.21 ; JUSB2.13 26.67,50.77 ; JUSB2.13 28.29,50.77 ; JUSB2.13 25.04,50.77 ; JUSB2.13 28.29,49.94 ; JUSB2.13 25.04,49.94 ; JUSB2.7 19.99,42.09 ; JUSB2.7 19.17,42.92 ; JUSB2.7 19.8,42.72 ; JUSB2.7 19.8,41.45 ; JUSB2.7 18.34,42.09 ; JUSB2.7 19.17,41.26 ; JUSB2.7 18.53,42.72
  GND3 w0.254: 19.17,41.26 JUSB2.7 ; JUSB2.7 18.34,42.09 ; JUSB2.7 19.8,42.72 ; JUSB2.7 18.53,42.72 ; JUSB2.7 19.8,41.45 ; JUSB2.7 19.17,42.92 ; JUSB2.7 19.99,42.09 ; 27.08,1.52 JSD1.13 ; JSD1.13 29.21,3.07 ; JSD1.13 29.21,2.29 ; JSD1.13 29.21,1.52 ; JSD1.13 24.94,2.29 ; JSD1.13 24.94,1.52 ; JSD1.13 27.08,3.07 ; JSD1.13 24.94,3.07 ; H1.1 27.46,77.41 ; H1.1 26.12,74.24 ; H1.1 27.46,74.73 ; H1.1 27.95,76.07 ; H1.1 24.29,76.07 ; H1.1 24.77,77.41 ; H1.1 24.77,74.73 ; H1.1 26.12,77.9 ; 18.53,62.25 JUSB1.7 ; JUSB1.7 19.17,63.72 ; JUSB1.7 19.8,62.25 ; JUSB1.7 19.8,63.52 ; JUSB1.7 18.53,63.52 ; JUSB1.7 19.99,62.89 ; JUSB1.7 18.34,62.89 ; JUSB1.7 19.17,62.06 ; 24.94,27.72 JSD1.14 ; JSD1.14 29.21,28.49 ; JSD1.14 27.08,27.72 ; JSD1.14 27.08,29.27 ; JSD1.14 24.94,28.49 ; JSD1.14 24.94,29.27 ; JSD1.14 29.21,27.72 ; JUSB1.12 28.29,55.04 ; JUSB1.12 25.04,55.04 ; JUSB1.12 25.04,54.21 ; JUSB1.12 26.67,54.21 ; JUSB1.12 28.29,54.21 ; JUSB2.4 20.67,46.42 ; JUSB2.4 20.03,44.95 ; JUSB2.4 20.67,44.76 ; 19.74,54.24 H3.1 ; H3.1 19.29,52.97 ; H3.1 22.29,54.24 ; H3.1 22.75,52.97 ; H3.1 21.02,51.24 ; H3.1 19.74,51.7 ; H3.1 21.02,54.7 ; H3.1 22.29,51.7 ; 20.49,31.93 H5.1 ; H5.1 20.49,33.76 ; H5.1 22.08,30.1 ; H5.1 23.67,30.1 ; H5.1 22.08,33.76 ; H5.1 23.67,33.76 ; H5.1 23.67,31.93 ; H5.1 20.49,30.1 ; H4.1 19.75,31.52 ; H4.1 16.98,30.35 ; H4.1 16.57,31.52 ; H4.1 19.33,32.69 ; H4.1 18.16,33.11 ; H4.1 19.33,30.35 ; H4.1 16.98,32.69 ; H4.1 18.16,29.93 ; 16.52,51.14 H2.1 ; H2.1 18.35,52.97 ; H2.1 17.86,51.63 ; H2.1 15.17,51.63 ; H2.1 17.86,54.31 ; H2.1 14.69,52.97 ; H2.1 15.17,54.31 ; H2.1 16.52,54.8 ; JUSB2.13 28.29,49.94 ; JUSB2.13 28.29,50.77 ; JUSB2.13 25.04,50.77 ; JUSB2.13 26.67,50.77 ; JUSB2.13 25.04,49.94 ; 18.64,70.12 JUSB1.11 ; JUSB1.11 20.07,68.46 ; JUSB1.11 18.64,69.29 ; JUSB1.11 20.07,70.12 ; JUSB1.11 18.64,68.46 ; 26.67,33.41 JUSB2.12 ; JUSB2.12 25.04,33.41 ; JUSB2.12 28.29,34.24 ; JUSB2.12 28.29,33.41 ; JUSB2.12 25.04,34.24 ; JUSB2.10 20.07,36.52 ; JUSB2.10 18.64,34.86 ; JUSB2.10 18.64,35.69 ; JUSB2.10 20.07,34.86 ; JUSB2.10 18.64,36.52 ; 18.64,56.49 JUSB1.10 ; JUSB1.10 20.07,55.66 ; JUSB1.10 20.07,57.32 ; JUSB1.10 18.64,57.32 ; JUSB1.10 18.64,55.66 ; JUSB1.13 28.29,70.74 ; JUSB1.13 25.04,70.74 ; JUSB1.13 28.29,71.57 ; JUSB1.13 25.04,71.57 ; JUSB1.13 26.67,71.57 ; 20.07,47.66 JUSB2.11 ; JUSB2.11 18.64,48.49 ; JUSB2.11 18.64,49.32 ; JUSB2.11 18.64,47.66 ; JUSB2.11 20.07,49.32 ; 20.03,65.75 JUSB1.4 ; JUSB1.4 20.67,65.56 ; JUSB1.4 20.67,67.22
  BOTTOM w0.254: v1(10.81,68.99) 10.7,69.11 UT1.21 ; UT1.10 10.7,74.66 v1(10.75,74.71) ; UT2.10 v1(11.43,46.05)
  BOTTOM w0.305: UT2.21 11.43,41.95 v1(11.18,42.2) ; JIO2.28 18.2,17.35 18.15,17.3 v1(16.59,17.3)
  BOTTOM w0.381: CR8.2 22.61,21.7 CR7.2 ; CT23.2 9.76,38.55 CT26.2 ; CR9.2 v1(24.61,25.76) ; CR3.2 22.22,20.4 v1(22.22,20.75) ; CHS3.1 16.82,74.44 v1(16.87,74.39) ; v1(21.16,21.24) 21.16,20.41 22.24,19.33 CR5.2 22.48,18.99 CR6.2 22.97,18.28 23.56,17.68 RR1.2 ; v1(7,67.32) 7.27,67.05 CT14.2 ; CR4.2 29.6,25.51 CR13.2 30.24,25.18 v1(30.57,25.51) ; CR14.2 v1(27.07,25.76)
  BOTTOM w0.406: D1.3 v1(17.17,62.26)
  BOTTOM w0.508: v1(15.48,73.39) RT16.2 RT18.2 ; RT1.2 v1(8.15,76.31) ; v1(6.69,66.77) 6.69,65.91 D4.1 ; v1(6.07,47.77) 6.8,47.03 RT32.2 ; JIO2.41 30.05,7.84 v1(30.05,8.03) ; v1(5.29,71.28) RT24.2 RT26.2 ; v1(5.37,74.58) RT28.2 RT2.2 ; CHS2.2 v1(17.24,73.55) ; RT35.2 RT41.2 v1(16.02,39.42) ; v1(9.13,37.15) 9.59,37.61 CT23.2 ; RT22.2 v1(5.29,67.98) ; JIO2.42 11.18,20.82 v1(11.13,21.43) ; RT37.2 RT39.2 v1(16.02,42.72) ; CR7.2 22.22,20.97 v1(22.22,20.75) ; CR12.2 22.83,24.35 22.47,24.35 v1(22.24,24.12) ; RT20.2 RT14.2 v1(15.48,70.09)
  vias: v1(0.43,76.55) v1(0.43,74.01) v1(0.43,71.47) v1(0.43,68.93) v1(0.43,66.39) v1(1.43,78.89) v1(2.58,65.03) v1(3.51,79.76) v1(3.57,62.69) v1(4.02,50.94) v1(4.86,53.33) v1(4.91,48.56) v1(5.35,57.93) v1(5.54,80.42) v1(5.81,46.18) v1(6.15,55.52) v1(6.66,43.79) v1(7.29,15.49) v1(7.39,41.36) v1(7.84,18.27) v1(7.99,38.89) v1(8.08,46.96) v1(8.46,36.39) v1(8.38,21.01) v1(8.75,23.7) v1(8.78,49.79) v1(8.78,48.03) v1(8.79,33.87) v1(8.92,80.31) v1(8.96,57.91) v1(8.96,26.26) v1(8.98,31.34) v1(9.04,28.8) v1(9.33,67.06) v1(9.3,21.22) v1(9.32,13.32) v1(9.45,71.86) v1(9.45,70.85) v1(9.55,52.42) v1(9.55,50.67) v1(9.92,75.66) v1(9.99,58.71) v1(10.18,43.2) v1(10.18,42.2) v1(10.45,72.86) v1(10.45,71.86) v1(10.45,70.85) v1(10.76,11.38) v1(10.85,66.58) v1(10.94,23.72) v1(11.07,26.32) v1(11.18,44.21) v1(11.18,43.2) v1(11.46,76.96) v1(11.45,72.86) v1(11.45,71.86) v1(11.45,70.85) v1(11.38,37.37) v1(11.59,78.89) v1(11.84,8.77) v1(12.19,43.2) v1(12.19,42.2) v1(12.27,63.47) v1(12.35,6.29) v1(12.45,66.93) v1(12.53,62.2) v1(12.86,3.8) v1(12.91,60.54) v1(12.97,23.21) v1(13.14,33.75) v1(13.16,21.75) v1(13.1,20.48) v1(13.61,23.78) v1(13.61,19.91) v1(13.86,39.34) v1(13.97,1.51) v1(14.13,78.89) v1(15.51,65.69) v1(15.51,64.85) v1(16.15,65.69) v1(16.15,64.85) v1(16.26,0.43) v1(16.3,37.26) v1(16.67,78.89) v1(19.14,0.77) v1(19.21,78.89) v1(19.96,19.98) v1(21.23,79.48) v1(21.33,0.76) v1(21.43,70.43) v1(22.75,49.27) v1(23.56,34.91) v1(23.94,70.07) v1(23.87,0.76) v1(24.04,55.71) v1(24.74,16.44) v1(25.15,82.12) v1(25.44,8.98) v1(25.55,84.3) v1(25.54,11.87) v1(25.61,10.19) v1(26.01,22.23) v1(26.01,21.11) v1(26.01,19.99) v1(26.21,15.73) v1(26.35,86.71) v1(26.41,0.76) v1(27.13,22.23) v1(27.13,21.11) v1(27.13,19.99) v1(27.19,8.98) v1(27.83,12.41) v1(27.81,10.16) v1(28.25,22.23) v1(28.25,21.11) v1(28.25,19.99) v1(28.64,71.42) v1(28.64,54.22) v1(28.64,51.68) v1(28.64,34.7) v1(28.64,32.16) v1(28.64,29.62) v1(28.89,86.71) v1(28.95,0.76) v1(30.87,28.41) v1(31.21,85.69) v1(31.28,83.15) v1(31.28,80.61) v1(31.28,78.07) v1(31.98,26.12) v1(31.98,23.58) v1(31.98,21.04) v1(31.98,18.5) v1(31.98,15.96) v1(31.98,13.42) v1(31.98,10.88) v1(31.98,8.34) v1(31.98,5.8) v1(31.98,3.26) v2(5.35,51.66) v2(13.48,59.02) v2(24.27,52.48)
+CARD_3V3: length 33.9
  TOP w0.117: CR15.1 12.73,14.08 v2(11.83,13.17)
  IN1 w1.016: 24.27,19.84 25.16,18.95 25.16,18.38 29.1,14.44 29.1,8.79 27.26,6.95 21.96,6.95 14.22,14.7
  vias: v1(13.35,15.65) v1(13.35,14.95) v1(23.51,20.67) v1(24.08,20.85)
CLK_PCIE_N4: length 16.2
  BOTTOM w0.117: JIO2.32 17.41,19.62 17.8,19.68 18.11,20.1 18.49,20.61 v4(19.36,20.61) 20.22,20.61 20.61,20.22 20.61,20.18 21.48,19.31 21.48,18.93 24.51,15.91 24.87,15.91 25.44,15.34 26.02,15.34 26.04,15.32 26.48,15.32 26.62,15.46 26.62,16.65 26.59,16.68 26.59,17.23 26.62,17.25 26.62,18.58 26.53,18.66 UCR1.6
CLK_PCIE_P4: length 16.3
  BOTTOM w0.117: JIO2.31 17.76,19.26 18.61,20.39 19.06,20.39 19.08,20.36 19.63,20.36 19.66,20.39 20.13,20.39 20.39,20.13 20.39,20.09 21.26,19.22 21.26,18.84 24.41,15.68 24.78,15.68 25.35,15.11 25.93,15.11 25.95,15.09 26.57,15.09 26.84,15.36 v4(26.84,16.95) 26.84,18.54 26.93,18.63 UCR1.5
CLKREQ_PCIE#4: length 38.9
  IN2 w0.127: v1(14.82,18.14) 14.82,18.58 21.04,24.8 26.69,24.8 29.43,22.05 29.43,18.78 v1(28.97,18.32)
  BOTTOM w0.117: v1(28.97,18.32) 28.4,18.32 28.13,18.59 UCR1.2 ; JIO2.33 16.23,18.89 15.58,18.89 v1(14.82,18.14) 10.1,18.14 9.2,19.04 9.2,19.68 10.23,20.71 10.23,21.36 11.51,22.64 v3(11.51,24.22)
I2C_EN1_U1: length 1.4
  BOTTOM w0.117: RT30.2 9.2,68.59 UT1.24
I2C_EN1_U2: length 1.6
  BOTTOM w0.117: RT51.2 9.93,40.44 UT2.24
LID_SW#: length 109.2
  TOP w0.117: v1(29.96,84.67) UHS1.3
  IN1 w0.102: v1(29.96,84.67) 29.96,84.66 28.11,82.82 27.38,82.82 17.24,72.67 v1(17.24,72.64) ; v1(16.59,72.03) 17.04,71.59 17.04,63.66 12.1,58.72 12.1,46.99 13.42,45.67 13.42,42.78 14.25,41.95 14.25,40.82 13.42,39.98 13.42,35.52 12.63,34.74 12.63,31.3 16.53,27.4 19.51,27.4 v1(19.96,26.95)
  IN2 w0.127: v1(17.35,12.92) 16.91,13.36 16.91,15.4 14.31,18.01 14.31,18.76 20.59,25.05 20.59,26.32 v1(19.96,26.95)
  BOTTOM w0.117: v1(17.35,12.92) 19.77,10.51 19.77,10.48 22.15,8.09 27.58,8.09 28.73,9.25 28.76,9.29 28.95,9.54 29.24,9.58 JIO2.1 30.05,10.64 v3(30.05,12.29) ; v1(17.24,72.64) CHS2.1 v1(16.59,72.03)
ON/OFF#: length 104.7
  TOP w0.117: v1(7.38,66.5) 7.41,66.53 7.41,67.82 5.7,69.53 5.7,73.16 4.57,74.3 SW1.3 5.68,75.76 5.81,75.63 6.15,75.63 6.28,75.76 SW1.4 ; v1(14.3,47.31) D2.4 14.29,48.21 13.5,49 13.47,49 11.56,50.92 11.56,58.44 10.59,59.4 v1(10.03,59.4)
  IN1 w0.102: v1(6.95,52.53) 7.68,51.8 7.68,45.59 8.43,44.83 8.43,40.83 9.67,39.59 9.67,35.5 9.92,35.25 9.92,25.68 11.35,24.26 11.35,22.99 16.52,17.81 16.65,17.81 17.29,17.18 17.29,16.99 20.33,13.96 20.33,12.52 22.56,10.28 v1(22.56,8.94)
  BOTTOM w0.117: v1(10.03,59.4) 10.03,61.06 9.23,61.86 8.38,61.86 7.92,62.32 7.92,63.48 8.39,63.96 8.39,65.49 v1(7.38,66.5) ; JIO2.11 25.12,12.4 22.68,9.96 22.68,9.22 22.56,9.1 v1(22.56,8.94) ; v1(14.3,47.31) 14.3,49.05 10.22,53.14 7.56,53.14 v1(6.95,52.53)
P3_U1_A_DE0: length 3
  BOTTOM w0.117: RT25.2 RT26.1 7.33,70.89 7.33,71.15 7.79,71.61 UT1.3
P3_U1_A_DE1: length 5.1
  BOTTOM w0.117: UT1.6 7.9,73.11 7.51,73.5 7.51,73.97 RT28.1 RT27.2 6.89,76.1 6.32,76.67 v3(5.9,76.67)
P3_U1_A_EQ0: length 8.7
  BOTTOM w0.117: UT1.2 7.72,71.11 7.58,70.96 7.58,70.79 7.33,70.55 7.33,69.24 RT21.2 RT22.1 6.89,67.87 6.37,67.34 5.29,67.34 4.78,67.85 4.78,68.86 v3(4.15,69.5)
P3_U1_A_EQ1: length 2.3
  BOTTOM w0.117: RT24.1 RT23.2 6.9,72.11 UT1.4
P3_U1_B_DE0: length 2.3
  BOTTOM w0.117: UT1.16 13.82,71.61 RT17.2 RT18.1
P3_U1_B_DE1: length 4.5
  BOTTOM w0.117: v3(13.96,67.18) RT19.2 RT20.1 13.42,69.81 13.42,70.45 13.26,70.61 UT1.18
P3_U1_B_EQ0: length 2.4
  BOTTOM w0.117: RT14.1 RT13.2 13.77,71.11 UT1.17
P3_U1_B_EQ1: length 3
  BOTTOM w0.117: UT1.15 13.04,72.11 13.48,72.55 13.48,72.92 RT16.1 RT15.2
P3_U2_A_DE0: length 7.1
  TOP w0.117: RT46.2 RT47.1 9.73,39.21 v1(9.21,39.21) 8.97,39.21 v3(8.53,39.65)
  BOTTOM w0.117: UT2.3 8.87,42.95 8.26,42.34 8.26,41.43 8.83,40.87 8.83,40.37 8.9,40.3 8.9,39.47 9.16,39.21 v1(9.21,39.21)
P3_U2_A_DE1: length 4.5
  TOP w0.117: RT49.1 RT48.2 v1(8.2,45.67)
  BOTTOM w0.117: v3(7.32,44.99) 8.01,45.67 v1(8.2,45.67) 8.2,45 8.74,44.45 UT2.6
P3_U2_A_EQ0: length 5
  TOP w0.117: RT43.1 9.85,40.73 RT42.2 v1(9.24,40.74) 8.97,40.74 v3(8.34,41.37)
  BOTTOM w0.117: UT2.2 8.87,42.45 8.5,42.08 8.5,41.58 9.24,40.85 v1(9.24,40.74)
P3_U2_A_EQ1: length 9.3
  TOP w0.117: v3(8.76,37.94) 8.57,38.13 8.57,38.49 8.65,38.57 v1(8.97,38.57) 8.97,38.32 RT44.2 RT45.1
  BOTTOM w0.117: UT2.4 8.87,43.45 8.02,42.6 8.02,41.3 8.58,40.74 8.58,40.27 8.66,40.2 8.66,39.14 8.97,38.83 v1(8.97,38.57)
P3_U2_B_DE0: length 2.2
  BOTTOM w0.117: UT2.16 14.26,42.95 RT39.1 RT38.2
P3_U2_B_DE1: length 6.8
  BOTTOM w0.117: v3(15.07,36.1) 15.26,36.29 15.26,37.81 14.5,38.57 RT40.2 RT41.1 13.23,40.68 UT2.18
P3_U2_B_EQ0: length 3.1
  BOTTOM w0.117: UT2.17 13.8,42.45 14.06,42.19 14.06,41.51 RT34.2 RT35.1
P3_U2_B_EQ1: length 2.1
  BOTTOM w0.117: RT36.2 RT37.1 14.41,43.45 UT2.15
PCI_RST#: length 37.9
  IN2 w0.127: v1(16.84,16.72) 19,18.89 19,21.87 21.67,24.54 26.58,24.54 29.01,22.11 v1(29.01,19.06)
  BOTTOM w0.117: UCR1.1 v1(29.01,19.06) ; v3(10.05,21.95) 9.87,21.77 9.87,21.2 8.92,20.25 8.92,18.04 10.04,16.92 16.21,16.92 16.41,16.72 v1(16.84,16.72) 16.91,16.79 19.64,16.79 JIO2.25
PCIE_CRX_C_DTX_N9: length 1.8
  BOTTOM w0.117: CR2.2 25.54,17.66 25.54,18.11 25.82,18.38 25.82,18.55 25.73,18.64 UCR1.8
PCIE_CRX_C_DTX_P9: length 1.8
  BOTTOM w0.117: CR1.2 25.77,17.63 25.77,18.01 26.04,18.29 26.04,18.56 26.13,18.65 UCR1.7
PCIE_CRX_DTX_N9: length 10.7
  IN2 w0.127: v1(25.35,16.25) 25.53,16.07 25.53,15.84 25.4,15.71 24.27,15.71 20.82,19.17 20.18,19.17 v1(19.96,19.39)
  BOTTOM w0.117: JIO2.30 17.97,18.71 18.19,19 18.45,19.04 18.59,19.22 v4(19.32,19.22) 19.49,19.22 19.5,19.22 19.79,19.22 v1(19.96,19.39) ; CR2.1 25.53,16.71 25.53,16.43 v1(25.35,16.25)
PCIE_CRX_DTX_P9: length 10.8
  IN2 w0.127: v1(25.93,16.25) 25.75,16.07 25.75,15.75 25.49,15.49 24.18,15.49 20.72,18.94 20.11,18.94 v1(19.97,18.81)
  BOTTOM w0.117: CR1.1 25.75,16.71 25.75,16.43 v1(25.93,16.25) ; JIO2.29 18.37,18.4 18.57,18.67 18.55,18.81 18.7,19 19.02,19 19.05,18.97 19.59,18.97 19.62,19 19.78,19 v1(19.97,18.81)
PCIE_CTX_DRX_N9: length 14.1
  BOTTOM w0.117: UCR1.4 27.33,18.69 27.45,18.58 27.45,16.21 27.42,16.18 27.42,15.63 27.45,15.61 27.45,15.37 26.75,14.67 v4(26.26,14.67) 25.76,14.67 25.74,14.69 25.17,14.69 24.6,15.26 24.24,15.26 21.18,18.32 19.73,18.32 19.6,18.14 19.4,18.11 JIO2.27
PCIE_CTX_DRX_P9: length 14.2
  BOTTOM w0.117: JIO2.26 19.79,17.8 19.77,18 19.84,18.09 21.09,18.09 24.15,15.04 24.51,15.04 25.08,14.47 25.65,14.47 25.67,14.45 25.95,14.45 25.98,14.42 26.53,14.42 26.56,14.45 26.84,14.45 27.67,15.28 v4(27.67,15.91) 27.67,18.6 27.73,18.66 UCR1.3
PCIE_WAKE#: length 2.6
  BOTTOM w0.117: UCR1.32 29.48,19.71 29.57,19.63 29.57,18.04 RR4.2
PD#_1_U1: length 2.5
  BOTTOM w0.117: UT1.5 7.22,72.61 RT31.2 RT2.1
PD#_1_U2: length 4.8
  TOP w0.117: v1(7.27,43.95) 7.58,43.95 RT33.1 RT52.2
  BOTTOM w0.117: v3(7.59,43.13) 7.59,43.73 7.37,43.95 ; 7.37,43.95 v1(7.27,43.95) ; 7.37,43.95 UT2.5
PWR_LED#: length 59.9
  IN1 w0.203: v1(20,21.56) 19.18,21.56 10.98,29.76 10.98,35.96 10.72,36.21 10.72,41.69 10.7,41.71 10.7,44.33 10.18,44.86 10.18,49.13 8.05,51.26 8.05,59.18 8.34,59.47 v1(8.34,59.75)
  IN2 w0.203: v1(20,21.56) 19.39,20.94 19.39,18.25 17.31,16.18 17.31,14.36 v1(17.54,14.13)
  BOTTOM w0.117: JIO2.21 21.27,15.61 21.03,15.58 20.42,14.79 19.96,14.79 19.3,14.13 v1(17.54,14.13)
  BOTTOM w0.203: v1(8.34,59.75) 8.34,61.03 RS1.1 7.38,61.04 v3(7.12,60.77)
PWR_LED#_R: length 37.8
  TOP w0.203: LED3.1 18.9,76.08 18.3,76.68 15.12,76.68 14.16,75.72 10.56,75.72 9.49,76.8 4.48,76.8 3.84,76.16 3.84,74.79 v1(2.94,73.88)
  IN1 w0.203: v1(2.94,73.88) 2.94,68 v1(4.39,66.54)
  BOTTOM w0.203: v1(4.39,66.54) 6.74,64.2 D4.3 8,61.55 8.75,61.55 RS1.2 9.26,59.8 8.61,59.15 v3(8.21,59.15)
PWR_LED_AMBER#: length 76.9
  TOP w0.203: v1(13.75,41.23) 13.75,41.23 v2(15.02,42.51) 15.02,47.42 ; RS2.1 v1(16.25,67.04) ; 13.65,49.44 12,51.1 12,55.06 v1(13.52,56.58)
  IN2 w0.203: v1(13.52,56.58) 14.4,57.45 14.4,65.59 15.85,67.04 v1(16.25,67.04) ; v1(22.64,13.91) 23.36,14.64 26.22,14.64 28.59,17.01 29.37,17.01 31,18.64 31,22.67 29.96,23.71 29.96,26.43 29.29,27.11 21.19,27.11 20.56,27.74 15.26,27.74 14.75,28.24 14.75,33.02 14.97,33.24 14.97,40.01 v1(13.75,41.23)
  BOTTOM w0.203: v1(22.64,13.91) 23.15,13.97 JIO2.16
PWR_LED_AMBER#_R: length 27.2
  TOP w0.203: RS2.2 14.22,67.04 13.62,66.44 12.24,66.44 11.98,66.18 v1(11.98,66.17) ; v1(9.06,66.51) 8.88,66.7 8.88,67.74 10.87,69.73 10.97,69.73 14.63,73.38 14.63,74.84 15.6,75.81 LED3.3
  BOTTOM w0.203: v1(9.06,66.51) 9.06,64.09 8.67,63.69 D4.2 10.19,62.81 11.98,64.6 v1(11.98,66.17)
SD_CD#: length 27.6
  TOP w0.117: JSD1.10 15.95,4.34 19.89,8.29 27.41,8.29 30.02,10.9 v1(30.02,20.06)
  BOTTOM w0.117: UCR1.30 29.57,20.51 v1(30.02,20.06)
SD_CLK: length 2.4
  BOTTOM w0.117: RR3.1 25.25,23.21 25.69,23.21 UCR1.17
SD_CLK_R: length 23.4
  TOP w0.117: v1(23.83,26.07) 23.09,26.07 18.81,21.79 18.81,15.4 18.18,14.76 18.18,11.13 17.55,10.51 17.06,10.51 JSD1.5
  BOTTOM w0.117: RR3.2 23.12,25.46 CR12.1 23.63,26.07 23.83,26.07 v1(23.83,26.07)
SD_CMD: length 2.3
  BOTTOM w0.117: UCR1.19 26.53,23.81 26.33,24.01 26.12,24.01 25.88,24.26 25.6,24.26 25.49,24.36 25.49,24.37 RR10.1
SD_CMD_R: length 22.2
  TOP w0.117: v1(25.23,25.76) 24.48,26.51 22.99,26.51 18.33,21.85 18.33,16.89 18.12,16.67 17.86,16.67 17.61,16.92 17.61,18 17.54,18.06 17.32,18.06 17.21,18.18 17.21,18.77 17.09,18.89 16.73,18.89 16.61,18.77 16.61,18.18 16.5,18.06 15.7,18.06 14.83,18.94 14.83,19.29 JSD1.2
  BOTTOM w0.117: RR10.2 v1(25.23,25.76)
SD_D0: length 1.8
  BOTTOM w0.117: UCR1.16 24.72,22.51 23.85,23.38 RR6.1
SD_D0_R: length 23.5
  TOP w0.117: v1(24.59,23.27) 22.83,23.27 22.7,23.14 21.92,23.14 21.67,22.89 21.67,22.35 20.46,21.14 20.46,13.58 20.37,13.48 20.37,12.38 19.19,11.21 19.19,10.83 15.64,7.27 JSD1.7
  BOTTOM w0.117: RR6.2 23.04,23.56 23.22,23.74 24.12,23.74 v1(24.59,23.27)
SD_D1: length 1.7
  BOTTOM w0.117: UCR1.15 24.67,22.11 24.03,22.75 RR7.1
SD_D1_R: length 24.5
  TOP w0.117: v1(22.5,23.56) 21.13,23.56 19.51,21.94 19.51,13.68 18.73,12.9 18.73,11.05 15.77,8.09 14.6,8.09 14.11,7.61 14.11,6.83 JSD1.8
  BOTTOM w0.117: RR7.2 22.95,22.75 22.56,23.14 22.56,23.49 v1(22.5,23.56)
SD_D2: length 1.8
  BOTTOM w0.117: RR9.1 26.48,24.56 27.33,23.71 UCR1.21
SD_D2_R: length 23.5
  TOP w0.117: v1(26.48,25.76) 24.97,27.27 22.65,27.27 22.26,26.88 22.09,26.88 21.68,27.3 21.51,27.3 21.34,27.14 21.34,26.97 21.76,26.55 21.76,26.39 21.6,26.22 21.43,26.22 21.01,26.64 20.85,26.64 20.68,26.47 20.68,26.31 21.1,25.89 21.1,25.73 20.94,25.56 20.77,25.56 20.35,25.98 20.19,25.98 20.02,25.81 20.02,25.65 20.44,25.23 20.44,25.06 17.95,22.57 17.3,22.57 17.18,22.69 17.18,23.98 17.07,24.1 16.83,24.1 16.72,23.98 16.72,22.78 16.6,22.67 16.43,22.67 15.92,23.18 14.92,23.18 14.81,23.3 14.81,24.27 JSD1.9
  BOTTOM w0.117: RR9.2 v1(26.48,25.76)
SD_D3: length 2
  BOTTOM w0.117: UCR1.20 26.93,23.76 26.44,24.26 26.22,24.26 25.85,24.62 RR8.1
SD_D3_R: length 24
  TOP w0.117: JSD1.1 14.62,21.59 14.62,20.85 14.74,20.73 15.1,20.73 15.22,20.85 15.22,21.19 15.34,21.3 15.57,21.3 15.69,21.19 15.69,20.85 15.81,20.73 16.15,20.73 17.48,19.4 17.81,19.4 17.92,19.51 17.92,20.38 17.81,20.49 17.13,20.49 17,20.62 17,20.91 17.12,21.03 17.85,21.03 17.96,21.15 17.96,21.31 17.85,21.43 16.71,21.43 16.59,21.55 16.59,21.81 16.72,21.94 17.86,21.94 22.81,26.89 24.73,26.89 v1(25.85,25.76)
  BOTTOM w0.117: RR8.2 v1(25.85,25.76)
SD_WP: length 29.2
  TOP w0.117: JSD1.11 16.08,3.14 19.83,6.89 20.6,6.89 21.7,7.99 27.46,7.99 30.43,10.96 30.43,20.29 v1(30.02,20.7)
  BOTTOM w0.117: UCR1.29 29.81,20.91 v1(30.02,20.7)
TEST3_U1: length 4.9
  BOTTOM w0.117: v3(13.96,76.77) RT29.2 13.48,74.57 13.48,73.31 12.78,72.61 UT1.14
TEST3_U2: length 1.9
  BOTTOM w0.117: UT2.14 13.49,43.95 13.86,44.32 13.86,44.56 RT50.2
USB3_CRX_C_RD_DTX_N1: length 1.8
  BOTTOM w0.117: UT1.23 9.7,69.41 9.84,69.27 9.84,69 10.18,68.66 10.18,68.46 CT16.2
USB3_CRX_C_RD_DTX_N2: length 3.6
  BOTTOM w0.117: UT2.23 10.43,40.8 10.58,40.65 10.58,40.4 10.85,40.13 10.97,40.13 v4(11.26,39.85) 12.13,38.97 12.13,38.53 CT28.2
USB3_CRX_C_RD_DTX_P1: length 1.8
  BOTTOM w0.117: CT15.2 10.4,68.43 10.4,68.75 10.06,69.09 10.06,69.26 10.2,69.39 UT1.22
USB3_CRX_C_RD_DTX_P2: length 3.7
  BOTTOM w0.117: CT27.2 12.35,38.53 12.35,39.07 11.63,39.79 11.63,39.83 11.24,40.22 11.2,40.22 11.07,40.35 10.94,40.35 10.8,40.49 10.8,40.66 10.93,40.79 UT2.22
USB3_CRX_DTX_N1: length 68.3
  IN1 w0.102: v1(9.98,67.09) 9.99,67.08 9.99,63.01 11.11,61.89 11.11,59.42 10.72,59.03 10.72,45.24 11.59,44.38 11.59,40.59 12.15,40.04 12.15,36.05 11.43,35.34 11.43,30.81 16.04,26.21 18.98,26.21 19.77,25.41 19.77,24.02 20.56,23.23 20.56,21 20.57,21 20.57,20.78 20.99,20.36 20.99,20.1 21.58,19.52 21.58,16.88 24.53,13.94 24.53,11.24 24.83,10.93 25.09,10.93 25.29,10.74 v1(25.29,10.73)
  BOTTOM w0.117: v1(9.98,67.09) 10.16,67.27 10.16,67.51 CT16.1 ; JIO2.8 25.83,10.86 25.82,10.85 25.41,10.85 25.29,10.74 v1(25.29,10.73)
USB3_CRX_DTX_N2: length 19.1
  BOTTOM w0.117: JIO2.38 15.04,21.43 15.24,21.45 15.42,21.66 15.42,21.87 15.39,21.9 15.39,22.48 15.42,22.51 15.42,22.71 11.57,26.56 v4(11.57,35.97) 11.57,36.29 12.3,37.03 12.3,37.37 11.96,37.72 CT28.1
USB3_CRX_DTX_P1: length 68.3
  IN1 w0.102: v1(10.56,67.09) 10.56,66.9 10.49,66.83 10.3,66.83 10.18,66.71 10.18,63.09 11.3,61.97 11.3,59.34 10.91,58.95 10.91,45.32 11.78,44.45 11.78,40.67 12.34,40.11 12.34,35.97 11.63,35.26 11.63,30.88 16.11,26.4 19.05,26.4 19.96,25.49 19.96,24.1 20.75,23.31 20.75,21.08 20.76,21.07 20.76,20.86 21.18,20.44 21.18,20.18 21.77,19.59 21.77,16.96 24.72,14.02 24.72,11.32 24.91,11.12 25.09,11.12 25.29,11.32 v1(25.29,11.32)
  BOTTOM w0.117: v1(25.29,11.32) 25.29,11.32 25.54,11.08 25.71,11.08 26.08,11.55 26.03,11.88 26.03,11.91 26.02,11.94 JIO2.9 ; CT15.1 10.38,67.51 10.38,67.27 v1(10.56,67.09)
USB3_CRX_DTX_P2: length 19
  BOTTOM w0.117: CT27.1 12.53,36.93 11.82,36.22 11.82,35.66 11.79,35.63 11.79,26.65 15.64,22.8 v4(15.64,22.19) 15.64,21.58 15.45,21.34 15.45,21.15 JIO2.37
USB3_CTX_C_RD_DRX_N1: length 1.6
  BOTTOM w0.117: UT1.20 11.2,69.37 11.34,69.23 11.34,68.37 CT13.1
USB3_CTX_C_RD_DRX_N2: length 3.4
  BOTTOM w0.117: CT29.1 13.27,38.53 13.27,38.74 v4(12.67,39.34) 12.07,39.94 12.07,40.62 11.93,40.76 UT2.20
USB3_CTX_C_RD_DRX_P1: length 1.7
  BOTTOM w0.117: CT12.1 11.6,68.53 11.6,69.27 11.7,69.37 UT1.19
USB3_CTX_C_RD_DRX_P2: length 3.4
  BOTTOM w0.117: UT2.19 12.43,40.77 12.3,40.63 12.3,40.04 12.62,39.71 12.65,39.71 13.04,39.33 13.04,39.29 13.5,38.84 13.5,38.53 CT30.1
USB3_CTX_DRX_N1: length 68.7
  IN1 w0.102: v1(11.23,67.09) 11.26,67.06 11.26,62.58 11.7,62.13 11.7,59.17 11.5,58.97 11.5,46.74 12.82,45.43 12.82,35.77 12.03,34.98 12.03,31.05 16.28,26.8 19.26,26.8 20.5,25.56 20.5,24.13 21.59,23.04 21.59,20.35 22.18,19.76 22.18,17.24 25.99,13.43 25.99,10.51 26.2,10.3 26.43,10.3 v1(26.62,10.1)
  BOTTOM w0.117: CT13.2 11.42,67.5 11.42,67.29 v1(11.23,67.09) ; JIO2.5 27.21,10.19 26.71,10.19 v1(26.62,10.1)
USB3_CTX_DRX_N2: length 20.4
  BOTTOM w0.117: JIO2.35 15.98,20.21 16.22,20.54 16.46,20.58 16.66,20.84 16.66,21.08 16.63,21.11 16.63,21.66 16.66,21.68 16.66,22.38 12.21,26.82 12.21,35.51 v4(13.04,36.34) 13.45,36.75 13.45,37.3 13.1,37.65 CT29.2
USB3_CTX_DRX_P1: length 68.6
  IN1 w0.102: v1(26.62,10.69) 26.43,10.49 26.28,10.49 26.18,10.59 26.18,13.51 22.37,17.32 22.37,19.84 21.78,20.43 21.78,23.12 20.69,24.21 20.69,25.64 19.34,26.99 16.36,26.99 12.22,31.13 12.22,34.9 13.01,35.69 13.01,45.51 11.69,46.82 11.69,58.89 11.89,59.09 11.89,62.21 11.45,62.66 11.45,66.72 11.49,66.77 11.77,66.77 11.81,66.82 v1(11.81,67.09)
  BOTTOM w0.117: v1(11.81,67.09) 11.65,67.25 11.65,67.48 CT12.2 ; JIO2.6 27.35,11.21 27.37,10.9 27.38,10.8 27.1,10.42 26.9,10.42 v1(26.62,10.69)
USB3_CTX_DRX_P2: length 20.4
  BOTTOM w0.117: CT30.2 13.67,36.65 13.41,36.39 13.41,36.36 13.02,35.97 12.98,35.97 12.44,35.42 12.44,26.92 16.88,22.47 v4(16.88,21.38) 16.88,20.77 16.63,20.42 16.65,20.27 16.37,19.91 JIO2.34
USB3_RX3_CONN1_N1: length 16.8
  IN1 w0.102: v1(12.9,63.36) 13.09,63.16 13.24,63.16 13.35,63.28 13.35,71.59 11.57,73.37 10.75,73.37 9.99,74.14 9.99,74.79 v1(9.66,75.12)
  BOTTOM w0.117: v1(12.9,63.36) 13.08,63.18 13.28,63.18 RT54.1 ; UT1.8 9.7,74.35 9.95,74.61 9.95,74.82 9.83,74.95 9.83,74.95 v1(9.66,75.12)
USB3_RX3_CONN1_N1_R: length 13.1
  BOTTOM w0.117: RT54.2 14.85,63.12 14.97,63.12 15.11,63.26 D1.9 D1.1 16.97,63.26 17.11,63.12 17.28,63.12 17.76,63.61 17.76,64.18 17.65,64.29 17.05,64.29 16.72,64.63 16.72,67.47 16.97,67.71 v4(17.36,67.71) 17.78,67.71 18.13,67.36 18.13,66.18 18.31,66 19.05,66 19.17,66.12 JUSB1.5
USB3_RX3_CONN1_P1: length 16.8
  IN1 w0.102: v1(12.9,62.77) 13.09,62.97 13.32,62.97 13.54,63.2 13.54,71.67 11.65,73.56 10.83,73.56 10.18,74.21 10.18,75.06 v1(10.24,75.12)
  BOTTOM w0.117: v1(12.9,62.77) 13.08,62.95 13.28,62.95 RT53.1 ; v1(10.24,75.12) 10.18,75.06 10.18,74.39 10.2,74.37 UT1.9
